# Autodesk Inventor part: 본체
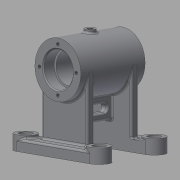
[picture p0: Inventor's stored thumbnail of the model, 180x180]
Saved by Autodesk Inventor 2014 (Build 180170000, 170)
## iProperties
Created: 2015-11
Part Number: 본체
Material: 일반
Document SubType Name: Modeling
Designer: Owner
Density: 1 g/cm^3
Appearance: 기본값
Author: Owner
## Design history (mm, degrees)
sketch "스케치1"
  geometry: C1 r 25 at (0, 0); 1 further point
  constraints: 1 centre point, 1 coincident
  dimensions: "d1" = 50 diameter of C1
extrude "돌출1" new body sketch "스케치1" stored distance "d2" = 70; taper "d3" = 0 deg
sketch "스케치2"
  geometry: C1 r 25 at (0, 0) reference; C2 r 16 at (0, 0)
  constraints: 1 centre point, 1 coincident
  dimensions: "d4" = 32 diameter of C2
extrude "돌출2" cut sketch "스케치2" distance "d5" = 12; taper "d6" = 0 deg
sketch "스케치3"
  geometry: C1 r 25 at (0, 0) reference; C2 r 16 at (0, 0)
  constraints: 1 centre point, 1 coincident
  dimensions: "d7" = 32 diameter of C2
extrude "돌출3" cut sketch "스케치3" distance "d8" = 12; taper "d9" = 0 deg
sketch "스케치4"
  geometry: C1 r 16 at (0, 0) reference; C2 r 14 at (0, 0)
  constraints: 1 centre point, 1 coincident
  dimensions: "d10" = 28 diameter of C2
extrude "돌출4" cut sketch "스케치4" stored distance "d11" = 12; taper "d12" = 0 deg
node "작업 평면1"
sketch "스케치6"
  geometry: L1 (0, 0)-(0, 40); L2 (0, 0)-(0, -40); L3 (0, 40)-(-40, 40); L4 (-40, 40)-(0, 40); L5 (0, 40)-(40, 40); L6 (0, -40)-(-40, -40); L7 (0, -40)-(40, -40); L8 (-40, 40)-(-40, 30); L9 (-40, -40)-(-40, -30); L10 (40, -40)-(40, -30); L11 (40, 40)-(40, 30); L12 (-40, 20)-(40, 20); L13 (-40, -20)-(40, -20); L14 (0, -20)-(4, -20); L15 (0, 20)-(0, 28); L16 (0, -20)-(0, -28); A1 r 10 centre (-40, 30) between (-40, 40) and (-40, 20); A2 r 10 centre (-40, -30) between (-40, -40) and (-40, -20); A3 r 10 centre (40, -30) between (40, -40) and (40, -20); A4 r 10 centre (40, 30) between (40, 40) and (40, 20)
  constraints: 32 end point, 8 equal length, 8 point on circle, 4 centre point, 4 coincident, 3 point on line, 2 midpoint, 2 perpendicular, 2 tangent, 1 vertical
  dimensions: "d14" = 40 distance of L1.start L1.end; "d15" = 40 distance of L1.start L2.end; "d16" = 40 distance of L1.end L3.end; "d17" = 40 distance of L1.end L5.end; "d18" = 40 distance of L2.end L6.end; "d19" = 40 distance of L2.end L7.end; "d20" = 10 distance of L3.end L8.end; "d21" = 10 distance of L6.end L9.end; "d24" = 10 distance of L7.end L10.end; "d25" = 10 distance of L5.end L11.end; "d27" = 4 distance of L14.start L14.end; "d32" = 8 distance of L15.start L15.end; "d33" = 8 distance of L14.start L16.end
extrude "돌출5" join sketch "스케치6" distance "d28" = 13; taper "d29" = 0 deg
extrude "돌출6" join sketch "스케치6" distance "d30" = 10; taper "d31" = 0 deg
sketch "스케치7"
  geometry: C1 r 16 at (0, 0) reference; C2 r 25 at (0, 0) reference
sketch "스케치8"
  geometry: L1 (0, -25)-(108.525, -25); L2 (0, 25)-(113.838, 25); C1 r 16 at (0, 0) reference; A1 r 25 centre (0, 0) between (0, -25) and (0, 25) reference; 1 further point
  constraints: 4 end point, 2 point on circle, 2 tangent, 1 horizontal, 1 parallel
  node "투영된 루프1"
sketch "스케치10"
  geometry: 1 further point
sketch "스케치11"
  geometry: L1 (-3.559, 0)-(-28.559, 0); L2 (0, 20)-(0, 28); L3 (0, 28)-(-25, 28); L4 (-25, 28)-(-25, 20); L5 (0, 28)-(25, 28); L6 (25, 28)-(25, 20); L7 (25, 20)-(-25, 20); L8 (0, -20)-(0, -28); L9 (0, -28)-(-25, -28); L10 (0, -28)-(25, -28); L11 (25, -28)-(25, -20); L12 (25, -20)-(-25, -20); L13 (-25, -20)-(-25, -28); 1 further point
  constraints: 26 end point, 7 perpendicular, 4 parallel, 1 collinear, 1 horizontal
  dimensions: "d34" = 25 distance of L1.start L1.end; "d35" = 8 distance of L2.start L2.end; "d36" = 25 distance of L2.end L3.end; "d37" = 25 distance of L2.end L5.end; "d38" = 8 distance of L8.start L8.end; "d39" = 25 distance of L8.end L9.end; "d40" = 25 distance of L8.end L10.end
extrude "돌출7" join sketch "스케치11" stored distance "d41" = 10; taper "d42" = 0 deg
sketch "스케치12"
  geometry: C1 r 25 at (0, 0) reference; A1 r 20 centre (0, 0) between (0, 20) and (-20, 0); 2 further points
  constraints: 4 point on circle, 1 centre point, 1 coincident
  dimensions: "d43" = 40 diameter of A1
hole "구멍1" sketch "스케치12" diameter "d44" = 3.242; stored, may be unused: countersink angle "d48" = 90 deg, drill point angle "d50" = 118 deg; dims "d45" = 8, "d46" = 19.05, "d47" = 4.775, "d49" = 10
hole "구멍2" sketch "스케치12" diameter "d51" = 3.242; stored, may be unused: countersink angle "d55" = 90 deg, drill point angle "d57" = 118 deg; dims "d52" = 8, "d53" = 19.05, "d54" = 4.775, "d56" = 10
sketch "스케치13"
  geometry: C1 r 25 at (0, 0) reference; A1 r 20 centre (0, 0) between (0, 20) and (-20, 0); 2 further points
  constraints: 4 point on circle, 1 centre point, 1 coincident
  dimensions: "d58" = 40 diameter of A1
hole "구멍3" sketch "스케치13" at (0, 20), (-20, 0), (0, -20), (20, 0) diameter "d59" = 3.242; stored, may be unused: countersink angle "d63" = 90 deg, drill point angle "d65" = 118 deg; dims "d60" = 8, "d61" = 19.05, "d62" = 4.775, "d64" = 10
sketch "스케치14"
  geometry: C1 r 10 at (0, 0) reference; C2 r 6 at (0, 0); C3 r 10 at (-60, 0) reference; C4 r 10 at (-60, -80) reference; C5 r 10 at (0, -80) reference; C6 r 6 at (0, -80); C7 r 6 at (-60, -80); C8 r 6 at (-60, 0); 1 further point
  constraints: 4 centre point, 4 coincident
  dimensions: "d66" = 12 diameter of C2; "d67" = 12 diameter of C6; "d68" = 12 diameter of C7; "d69" = 12 diameter of C8
extrude "돌출8" cut sketch "스케치14" distance "d70" = 4; taper "d71" = 0 deg
sketch "스케치15"
  geometry: C1 r 10 at (0, 0) reference; C2 r 6 at (0, 0); 1 further point
  constraints: 1 centre point, 1 coincident
  dimensions: "d72" = 12 diameter of C2
extrude "돌출9" cut sketch "스케치15" distance "d73" = 4; taper "d74" = 0 deg
sketch "스케치16"
  geometry: C1 r 10 at (0, 0) reference; C2 r 6 at (0, 0); 1 further point
  constraints: 1 centre point, 1 coincident
  dimensions: "d75" = 12 diameter of C2
extrude "돌출10" cut sketch "스케치16" distance "d76" = 4; taper "d77" = 0 deg
sketch "스케치17"
  geometry: C1 r 10 at (0, 0) reference; C2 r 6 at (0, 0); 1 further point
  constraints: 1 centre point, 1 coincident
  dimensions: "d78" = 12 diameter of C2
extrude "돌출11" cut sketch "스케치17" distance "d79" = 4; taper "d80" = 0 deg
sketch "스케치18"
  geometry: C1 r 6 at (0, 0) reference; C2 r 3 at (0, 0); 1 further point
  constraints: 1 centre point, 1 coincident
  dimensions: "d81" = 6 diameter of C2
extrude "돌출12" cut sketch "스케치18" stored distance "d82" = 4; taper "d83" = 0 deg
sketch "스케치19"
  geometry: C1 r 6 at (0, 0) reference; C2 r 3 at (0, 0); C3 r 10 at (0, -80) reference; C4 r 10 at (-60, -80) reference; C5 r 3 at (-60, -80); C6 r 3 at (0, -80); 1 further point
  constraints: 3 centre point, 3 coincident
  dimensions: "d84" = 6 diameter of C2; "d85" = 6 diameter of C5
extrude "돌출13" cut sketch "스케치19" stored distance "d86" = 4; taper "d87" = 0 deg
node "작업 평면2"
sketch "스케치20"
  geometry: L1 (0, -20)-(4, -20); L2 (0, -20)-(-4, -20); L3 (0, 20)-(-4, 20); L4 (0, 20)-(4, 20); L5 (4, 20)-(4, -20); L6 (-4, 20)-(-4, -20); 1 further point
  constraints: 12 end point, 3 equal length, 1 horizontal
  dimensions: "d89" = 4 distance of L1.start L1.end; "d90" = 4 distance of L1.start L2.end; "d91" = 4 distance of L3.start L3.end; "d92" = 4 distance of L3.start L4.end
extrude "돌출14" join sketch "스케치20" stored distance "d93" = 0; taper "d94" = 0 deg
sketch "스케치21"
  geometry: L1 (-20.322, 0)-(-20.322, 40) reference; L2 (0, 0)-(-20.322, 0) reference; L3 (0, 0)-(0, 40) reference; L4 (-20.322, 40)-(0, 40) reference; 1 further point
sketch "스케치22"
  geometry: L1 (-45, -20)-(-45, 20) reference; L2 (-45, 0)-(-25, 0); L3 (-45, 0)-(-35, 0); L4 (-35, 0)-(-35, 11.5); L5 (-35, 0)-(-35, -11.5); L6 (-38.5, 11.5)-(-38.5, -11.5); L7 (-31.5, 11.5)-(-31.5, -11.5); A1 r 3.5 centre (-35, 11.5) between (-38.5, 11.5) and (-31.5, 11.5); A2 r 3.5 centre (-35, -11.5) between (-38.5, -11.5) and (-31.5, -11.5); 1 further point
  constraints: 12 end point, 4 point on circle, 2 centre point, 2 coincident, 2 midpoint, 2 perpendicular, 2 tangent, 1 collinear
  dimensions: "d97" = 20 distance of L2.start L2.end; "d98" = 10 distance of L2.start L3.end; "d99" = 11.5 distance of L3.end L4.end; "d100" = 11.5 distance of L3.end L5.end; "d101" = 7 diameter of A1; "d102" = 7 diameter of A2
extrude "돌출15" cut sketch "스케치22" stored distance "d103" = 4; taper "d104" = 0 deg
node "작업 평면3"
sketch "스케치23"
  geometry: C1 r 5 at (0, 0); 1 further point
  constraints: 1 centre point, 1 coincident
  dimensions: "d106" = 10 diameter of C1
extrude "돌출16" join sketch "스케치23" stored distance "d107" = 4; taper "d108" = 0 deg
sketch "스케치24"
  geometry: C1 r 5 at (0, 0) reference; C2 r 3 at (0, 0)
  constraints: 1 centre point, 1 coincident
  dimensions: "d109" = 6 diameter of C2
hole "구멍4" sketch "스케치24" at (0, 0) diameter "d110" = 5.188; stored, may be unused: countersink angle "d114" = 90 deg, drill point angle "d116" = 118 deg; dims "d111" = 18, "d112" = 19.05, "d113" = 4.775, "d115" = 20
fillet "모깎기1" dims "d117" = 2
fillet "모깎기2" dims "d118" = 2
fillet "모깎기3" dims "d119" = 2
fillet "모깎기4" dims "d120" = 2
fillet "모깎기5" dims "d121" = 2
fillet "모깎기6" dims "d122" = 2
chamfer "모따기1" distance "d123" = 1; stored, may be unused: second distance "d124" = 2, angle "d125" = 45 deg
node "작업 평면5"
sketch "스케치26"
  geometry: 2 further points
  constraints: 1 coincident, 1 other
feature "엠보싱1" sketch "스케치26" dims "d127" = 0.5, "d128" = 0
node "솔리드1"
other parameters: "d13" = 68, "d88" = 45, "d105" = -28
